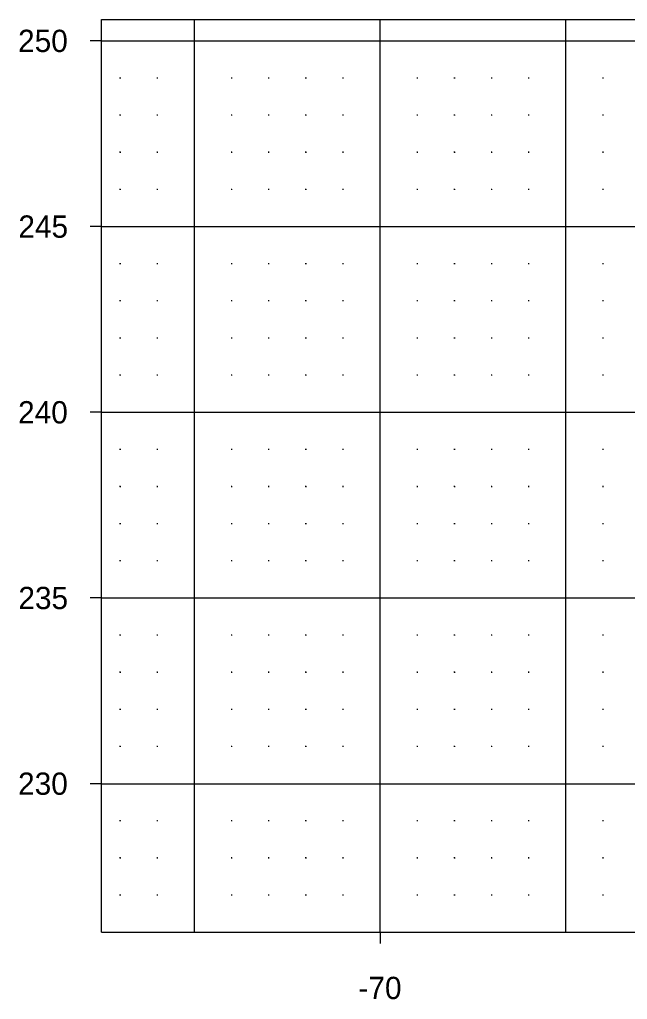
# Model space of a CAD drawing. Extents: x -80 to 80, y 222 to 253.
# Drawn here: x -79.7 to -63.34, y 224.19 to 250.57 of the extents above; entities that cross this region are included whole.
import ezdxf

# ---------------------------------------------------------------- set-up
doc = ezdxf.new("R2010")
doc.units = 0
for name, color, linetype in [('DSN_DRFT_XS Border Grid', 7, 'Continuous'), ('DSN_DRFT_XS Grid Annotations', 7, 'Continuous'), ('DSN_DRFT_XS Grid Major', 7, 'Continuous'), ('DSN_DRFT_XS Grid Minor', 7, 'Continuous')]:
    doc.layers.add(name, color=color, linetype=linetype)

msp = doc.modelspace()

# ---------------------------------------------------------------- linework, layer by layer
at = {"layer": 'DSN_DRFT_XS Border Grid'}
for p, q in [((-77.5, 250.573), (77.5, 250.573)), ((-77.5, 226), (-77.5, 250.573)), ((-77.5, 226), (77.5, 226))]:
    msp.add_line(p, q, dxfattribs=at)
at = {"layer": 'DSN_DRFT_XS Grid Major'}
for p, q in [((-75, 226), (-75, 250.573)), ((-70, 226), (-70, 250.573)), ((-65, 226), (-65, 250.573)), ((-77.5, 250), (-77.8, 250)), ((-77.5, 250), (77.5, 250)), ((-77.5, 245), (-77.8, 245)), ((-77.5, 245), (77.5, 245)), ((-77.5, 240), (-77.8, 240)), ((-77.5, 240), (77.5, 240)), ((-77.5, 235), (-77.8, 235)), ((-77.5, 235), (77.5, 235)), ((-77.5, 230), (-77.8, 230)), ((-77.5, 230), (77.5, 230)), ((-70, 226), (-70, 225.7))]:
    msp.add_line(p, q, dxfattribs=at)
at = {"layer": 'DSN_DRFT_XS Grid Minor'}
for p, q in [((-76.988, 249), (-77.012, 249)), ((-77, 249.012), (-77, 248.988)), ((-75.988, 249), (-76.012, 249)), ((-76, 249.012), (-76, 248.988)), ((-73.988, 249), (-74.012, 249)), ((-74, 249.012), (-74, 248.988)), ((-72.988, 249), (-73.012, 249)), ((-73, 249.012), (-73, 248.988)), ((-71.988, 249), (-72.012, 249)), ((-72, 249.012), (-72, 248.988)), ((-70.988, 249), (-71.012, 249)), ((-71, 249.012), (-71, 248.988)), ((-68.988, 249), (-69.012, 249)), ((-69, 249.012), (-69, 248.988)), ((-67.988, 249), (-68.012, 249)), ((-68, 249.012), (-68, 248.988)), ((-66.988, 249), (-67.012, 249)), ((-67, 249.012), (-67, 248.988)), ((-65.988, 249), (-66.012, 249)), ((-66, 249.012), (-66, 248.988)), ((-63.988, 249), (-64.012, 249)), ((-64, 249.012), (-64, 248.988)), ((-76.988, 248), (-77.012, 248)), ((-77, 248.012), (-77, 247.988)), ((-75.988, 248), (-76.012, 248)), ((-76, 248.012), (-76, 247.988)), ((-73.988, 248), (-74.012, 248)), ((-74, 248.012), (-74, 247.988)), ((-72.988, 248), (-73.012, 248)), ((-73, 248.012), (-73, 247.988)), ((-71.988, 248), (-72.012, 248)), ((-72, 248.012), (-72, 247.988)), ((-70.988, 248), (-71.012, 248)), ((-71, 248.012), (-71, 247.988)), ((-68.988, 248), (-69.012, 248)), ((-69, 248.012), (-69, 247.988)), ((-67.988, 248), (-68.012, 248)), ((-68, 248.012), (-68, 247.988)), ((-66.988, 248), (-67.012, 248)), ((-67, 248.012), (-67, 247.988)), ((-65.988, 248), (-66.012, 248)), ((-66, 248.012), (-66, 247.988)), ((-63.988, 248), (-64.012, 248)), ((-64, 248.012), (-64, 247.988)), ((-76.988, 247), (-77.012, 247)), ((-77, 247.012), (-77, 246.988)), ((-75.988, 247), (-76.012, 247)), ((-76, 247.012), (-76, 246.988)), ((-73.988, 247), (-74.012, 247)), ((-74, 247.012), (-74, 246.988)), ((-72.988, 247), (-73.012, 247)), ((-73, 247.012), (-73, 246.988)), ((-71.988, 247), (-72.012, 247)), ((-72, 247.012), (-72, 246.988)), ((-70.988, 247), (-71.012, 247)), ((-71, 247.012), (-71, 246.988)), ((-68.988, 247), (-69.012, 247)), ((-69, 247.012), (-69, 246.988)), ((-67.988, 247), (-68.012, 247)), ((-68, 247.012), (-68, 246.988)), ((-66.988, 247), (-67.012, 247)), ((-67, 247.012), (-67, 246.988)), ((-65.988, 247), (-66.012, 247)), ((-66, 247.012), (-66, 246.988)), ((-63.988, 247), (-64.012, 247)), ((-64, 247.012), (-64, 246.988)), ((-76.988, 246), (-77.012, 246)), ((-77, 246.012), (-77, 245.988)), ((-75.988, 246), (-76.012, 246)), ((-76, 246.012), (-76, 245.988)), ((-73.988, 246), (-74.012, 246)), ((-74, 246.012), (-74, 245.988)), ((-72.988, 246), (-73.012, 246)), ((-73, 246.012), (-73, 245.988)), ((-71.988, 246), (-72.012, 246)), ((-72, 246.012), (-72, 245.988)), ((-70.988, 246), (-71.012, 246)), ((-71, 246.012), (-71, 245.988)), ((-68.988, 246), (-69.012, 246)), ((-69, 246.012), (-69, 245.988)), ((-67.988, 246), (-68.012, 246)), ((-68, 246.012), (-68, 245.988)), ((-66.988, 246), (-67.012, 246)), ((-67, 246.012), (-67, 245.988)), ((-65.988, 246), (-66.012, 246)), ((-66, 246.012), (-66, 245.988)), ((-63.988, 246), (-64.012, 246)), ((-64, 246.012), (-64, 245.988)), ((-76.988, 244), (-77.012, 244)), ((-77, 244.012), (-77, 243.988)), ((-75.988, 244), (-76.012, 244)), ((-76, 244.012), (-76, 243.988)), ((-73.988, 244), (-74.012, 244)), ((-74, 244.012), (-74, 243.988)), ((-72.988, 244), (-73.012, 244)), ((-73, 244.012), (-73, 243.988)), ((-71.988, 244), (-72.012, 244)), ((-72, 244.012), (-72, 243.988)), ((-70.988, 244), (-71.012, 244)), ((-71, 244.012), (-71, 243.988)), ((-68.988, 244), (-69.012, 244)), ((-69, 244.012), (-69, 243.988)), ((-67.988, 244), (-68.012, 244)), ((-68, 244.012), (-68, 243.988)), ((-66.988, 244), (-67.012, 244)), ((-67, 244.012), (-67, 243.988)), ((-65.988, 244), (-66.012, 244)), ((-66, 244.012), (-66, 243.988)), ((-63.988, 244), (-64.012, 244)), ((-64, 244.012), (-64, 243.988)), ((-76.988, 243), (-77.012, 243)), ((-77, 243.012), (-77, 242.988)), ((-75.988, 243), (-76.012, 243)), ((-76, 243.012), (-76, 242.988)), ((-73.988, 243), (-74.012, 243)), ((-74, 243.012), (-74, 242.988)), ((-72.988, 243), (-73.012, 243)), ((-73, 243.012), (-73, 242.988)), ((-71.988, 243), (-72.012, 243)), ((-72, 243.012), (-72, 242.988)), ((-70.988, 243), (-71.012, 243)), ((-71, 243.012), (-71, 242.988)), ((-68.988, 243), (-69.012, 243)), ((-69, 243.012), (-69, 242.988)), ((-67.988, 243), (-68.012, 243)), ((-68, 243.012), (-68, 242.988)), ((-66.988, 243), (-67.012, 243)), ((-67, 243.012), (-67, 242.988)), ((-65.988, 243), (-66.012, 243)), ((-66, 243.012), (-66, 242.988)), ((-63.988, 243), (-64.012, 243)), ((-64, 243.012), (-64, 242.988)), ((-76.988, 242), (-77.012, 242)), ((-77, 242.012), (-77, 241.988)), ((-75.988, 242), (-76.012, 242)), ((-76, 242.012), (-76, 241.988)), ((-73.988, 242), (-74.012, 242)), ((-74, 242.012), (-74, 241.988)), ((-72.988, 242), (-73.012, 242)), ((-73, 242.012), (-73, 241.988)), ((-71.988, 242), (-72.012, 242)), ((-72, 242.012), (-72, 241.988)), ((-70.988, 242), (-71.012, 242)), ((-71, 242.012), (-71, 241.988)), ((-68.988, 242), (-69.012, 242)), ((-69, 242.012), (-69, 241.988)), ((-67.988, 242), (-68.012, 242)), ((-68, 242.012), (-68, 241.988)), ((-66.988, 242), (-67.012, 242)), ((-67, 242.012), (-67, 241.988)), ((-65.988, 242), (-66.012, 242)), ((-66, 242.012), (-66, 241.988)), ((-63.988, 242), (-64.012, 242)), ((-64, 242.012), (-64, 241.988)), ((-76.988, 241), (-77.012, 241)), ((-77, 241.012), (-77, 240.988)), ((-75.988, 241), (-76.012, 241)), ((-76, 241.012), (-76, 240.988)), ((-73.988, 241), (-74.012, 241)), ((-74, 241.012), (-74, 240.988)), ((-72.988, 241), (-73.012, 241)), ((-73, 241.012), (-73, 240.988)), ((-71.988, 241), (-72.012, 241)), ((-72, 241.012), (-72, 240.988)), ((-70.988, 241), (-71.012, 241)), ((-71, 241.012), (-71, 240.988)), ((-68.988, 241), (-69.012, 241)), ((-69, 241.012), (-69, 240.988)), ((-67.988, 241), (-68.012, 241)), ((-68, 241.012), (-68, 240.988)), ((-66.988, 241), (-67.012, 241)), ((-67, 241.012), (-67, 240.988)), ((-65.988, 241), (-66.012, 241)), ((-66, 241.012), (-66, 240.988)), ((-63.988, 241), (-64.012, 241)), ((-64, 241.012), (-64, 240.988)), ((-76.988, 239), (-77.012, 239)), ((-77, 239.012), (-77, 238.988)), ((-75.988, 239), (-76.012, 239)), ((-76, 239.012), (-76, 238.988)), ((-73.988, 239), (-74.012, 239)), ((-74, 239.012), (-74, 238.988)), ((-72.988, 239), (-73.012, 239)), ((-73, 239.012), (-73, 238.988)), ((-71.988, 239), (-72.012, 239)), ((-72, 239.012), (-72, 238.988)), ((-70.988, 239), (-71.012, 239)), ((-71, 239.012), (-71, 238.988)), ((-68.988, 239), (-69.012, 239)), ((-69, 239.012), (-69, 238.988)), ((-67.988, 239), (-68.012, 239)), ((-68, 239.012), (-68, 238.988)), ((-66.988, 239), (-67.012, 239)), ((-67, 239.012), (-67, 238.988)), ((-65.988, 239), (-66.012, 239)), ((-66, 239.012), (-66, 238.988)), ((-63.988, 239), (-64.012, 239)), ((-64, 239.012), (-64, 238.988)), ((-76.988, 238), (-77.012, 238)), ((-77, 238.012), (-77, 237.988)), ((-75.988, 238), (-76.012, 238)), ((-76, 238.012), (-76, 237.988)), ((-73.988, 238), (-74.012, 238)), ((-74, 238.012), (-74, 237.988)), ((-72.988, 238), (-73.012, 238)), ((-73, 238.012), (-73, 237.988)), ((-71.988, 238), (-72.012, 238)), ((-72, 238.012), (-72, 237.988)), ((-70.988, 238), (-71.012, 238)), ((-71, 238.012), (-71, 237.988)), ((-68.988, 238), (-69.012, 238)), ((-69, 238.012), (-69, 237.988)), ((-67.988, 238), (-68.012, 238)), ((-68, 238.012), (-68, 237.988)), ((-66.988, 238), (-67.012, 238)), ((-67, 238.012), (-67, 237.988)), ((-65.988, 238), (-66.012, 238)), ((-66, 238.012), (-66, 237.988)), ((-63.988, 238), (-64.012, 238)), ((-64, 238.012), (-64, 237.988)), ((-76.988, 237), (-77.012, 237)), ((-77, 237.012), (-77, 236.988)), ((-75.988, 237), (-76.012, 237)), ((-76, 237.012), (-76, 236.988)), ((-73.988, 237), (-74.012, 237)), ((-74, 237.012), (-74, 236.988)), ((-72.988, 237), (-73.012, 237)), ((-73, 237.012), (-73, 236.988)), ((-71.988, 237), (-72.012, 237)), ((-72, 237.012), (-72, 236.988)), ((-70.988, 237), (-71.012, 237)), ((-71, 237.012), (-71, 236.988)), ((-68.988, 237), (-69.012, 237)), ((-69, 237.012), (-69, 236.988)), ((-67.988, 237), (-68.012, 237)), ((-68, 237.012), (-68, 236.988)), ((-66.988, 237), (-67.012, 237)), ((-67, 237.012), (-67, 236.988)), ((-65.988, 237), (-66.012, 237)), ((-66, 237.012), (-66, 236.988)), ((-63.988, 237), (-64.012, 237)), ((-64, 237.012), (-64, 236.988)), ((-76.988, 236), (-77.012, 236)), ((-77, 236.012), (-77, 235.988)), ((-75.988, 236), (-76.012, 236)), ((-76, 236.012), (-76, 235.988)), ((-73.988, 236), (-74.012, 236)), ((-74, 236.012), (-74, 235.988)), ((-72.988, 236), (-73.012, 236)), ((-73, 236.012), (-73, 235.988)), ((-71.988, 236), (-72.012, 236)), ((-72, 236.012), (-72, 235.988)), ((-70.988, 236), (-71.012, 236)), ((-71, 236.012), (-71, 235.988)), ((-68.988, 236), (-69.012, 236)), ((-69, 236.012), (-69, 235.988)), ((-67.988, 236), (-68.012, 236)), ((-68, 236.012), (-68, 235.988)), ((-66.988, 236), (-67.012, 236)), ((-67, 236.012), (-67, 235.988)), ((-65.988, 236), (-66.012, 236)), ((-66, 236.012), (-66, 235.988)), ((-63.988, 236), (-64.012, 236)), ((-64, 236.012), (-64, 235.988)), ((-77, 234.012), (-77, 233.988)), ((-76, 234.012), (-76, 233.988)), ((-74, 234.012), (-74, 233.988)), ((-73, 234.012), (-73, 233.988)), ((-72, 234.012), (-72, 233.988)), ((-71, 234.012), (-71, 233.988)), ((-69, 234.012), (-69, 233.988)), ((-68, 234.012), (-68, 233.988)), ((-67, 234.012), (-67, 233.988)), ((-66, 234.012), (-66, 233.988)), ((-64, 234.012), (-64, 233.988)), ((-76.988, 234), (-77.012, 234)), ((-75.988, 234), (-76.012, 234)), ((-73.988, 234), (-74.012, 234)), ((-72.988, 234), (-73.012, 234)), ((-71.988, 234), (-72.012, 234)), ((-70.988, 234), (-71.012, 234)), ((-68.988, 234), (-69.012, 234)), ((-67.988, 234), (-68.012, 234)), ((-66.988, 234), (-67.012, 234)), ((-65.988, 234), (-66.012, 234)), ((-63.988, 234), (-64.012, 234)), ((-76.988, 233), (-77.012, 233)), ((-77, 233.012), (-77, 232.988)), ((-75.988, 233), (-76.012, 233)), ((-76, 233.012), (-76, 232.988)), ((-73.988, 233), (-74.012, 233)), ((-74, 233.012), (-74, 232.988)), ((-72.988, 233), (-73.012, 233)), ((-73, 233.012), (-73, 232.988)), ((-71.988, 233), (-72.012, 233)), ((-72, 233.012), (-72, 232.988)), ((-70.988, 233), (-71.012, 233)), ((-71, 233.012), (-71, 232.988)), ((-68.988, 233), (-69.012, 233)), ((-69, 233.012), (-69, 232.988)), ((-67.988, 233), (-68.012, 233)), ((-68, 233.012), (-68, 232.988)), ((-66.988, 233), (-67.012, 233)), ((-67, 233.012), (-67, 232.988)), ((-65.988, 233), (-66.012, 233)), ((-66, 233.012), (-66, 232.988)), ((-63.988, 233), (-64.012, 233)), ((-64, 233.012), (-64, 232.988)), ((-76.988, 232), (-77.012, 232)), ((-77, 232.012), (-77, 231.988)), ((-75.988, 232), (-76.012, 232)), ((-76, 232.012), (-76, 231.988)), ((-73.988, 232), (-74.012, 232)), ((-74, 232.012), (-74, 231.988)), ((-72.988, 232), (-73.012, 232)), ((-73, 232.012), (-73, 231.988)), ((-71.988, 232), (-72.012, 232)), ((-72, 232.012), (-72, 231.988)), ((-70.988, 232), (-71.012, 232)), ((-71, 232.012), (-71, 231.988)), ((-68.988, 232), (-69.012, 232)), ((-69, 232.012), (-69, 231.988)), ((-67.988, 232), (-68.012, 232)), ((-68, 232.012), (-68, 231.988)), ((-66.988, 232), (-67.012, 232)), ((-67, 232.012), (-67, 231.988)), ((-65.988, 232), (-66.012, 232)), ((-66, 232.012), (-66, 231.988)), ((-63.988, 232), (-64.012, 232)), ((-64, 232.012), (-64, 231.988)), ((-76.988, 231), (-77.012, 231)), ((-77, 231.012), (-77, 230.988)), ((-75.988, 231), (-76.012, 231)), ((-76, 231.012), (-76, 230.988)), ((-73.988, 231), (-74.012, 231)), ((-74, 231.012), (-74, 230.988)), ((-72.988, 231), (-73.012, 231)), ((-73, 231.012), (-73, 230.988)), ((-71.988, 231), (-72.012, 231)), ((-72, 231.012), (-72, 230.988)), ((-70.988, 231), (-71.012, 231)), ((-71, 231.012), (-71, 230.988)), ((-68.988, 231), (-69.012, 231)), ((-69, 231.012), (-69, 230.988)), ((-67.988, 231), (-68.012, 231)), ((-68, 231.012), (-68, 230.988)), ((-66.988, 231), (-67.012, 231)), ((-67, 231.012), (-67, 230.988)), ((-65.988, 231), (-66.012, 231)), ((-66, 231.012), (-66, 230.988)), ((-63.988, 231), (-64.012, 231)), ((-64, 231.012), (-64, 230.988)), ((-76.988, 229), (-77.012, 229)), ((-77, 229.012), (-77, 228.988)), ((-75.988, 229), (-76.012, 229)), ((-76, 229.012), (-76, 228.988)), ((-73.988, 229), (-74.012, 229)), ((-74, 229.012), (-74, 228.988)), ((-72.988, 229), (-73.012, 229)), ((-73, 229.012), (-73, 228.988)), ((-71.988, 229), (-72.012, 229)), ((-72, 229.012), (-72, 228.988)), ((-70.988, 229), (-71.012, 229)), ((-71, 229.012), (-71, 228.988)), ((-68.988, 229), (-69.012, 229)), ((-69, 229.012), (-69, 228.988)), ((-67.988, 229), (-68.012, 229)), ((-68, 229.012), (-68, 228.988)), ((-66.988, 229), (-67.012, 229)), ((-67, 229.012), (-67, 228.988)), ((-65.988, 229), (-66.012, 229)), ((-66, 229.012), (-66, 228.988)), ((-63.988, 229), (-64.012, 229)), ((-64, 229.012), (-64, 228.988)), ((-76.988, 228), (-77.012, 228)), ((-77, 228.012), (-77, 227.988)), ((-75.988, 228), (-76.012, 228)), ((-76, 228.012), (-76, 227.988)), ((-73.988, 228), (-74.012, 228)), ((-74, 228.012), (-74, 227.988)), ((-72.988, 228), (-73.012, 228)), ((-73, 228.012), (-73, 227.988)), ((-71.988, 228), (-72.012, 228)), ((-72, 228.012), (-72, 227.988)), ((-70.988, 228), (-71.012, 228)), ((-71, 228.012), (-71, 227.988)), ((-68.988, 228), (-69.012, 228)), ((-69, 228.012), (-69, 227.988)), ((-67.988, 228), (-68.012, 228)), ((-68, 228.012), (-68, 227.988)), ((-66.988, 228), (-67.012, 228)), ((-67, 228.012), (-67, 227.988)), ((-65.988, 228), (-66.012, 228)), ((-66, 228.012), (-66, 227.988)), ((-63.988, 228), (-64.012, 228)), ((-64, 228.012), (-64, 227.988)), ((-76.988, 227), (-77.012, 227)), ((-77, 227.012), (-77, 226.988)), ((-75.988, 227), (-76.012, 227)), ((-76, 227.012), (-76, 226.988)), ((-73.988, 227), (-74.012, 227)), ((-74, 227.012), (-74, 226.988)), ((-72.988, 227), (-73.012, 227)), ((-73, 227.012), (-73, 226.988)), ((-71.988, 227), (-72.012, 227)), ((-72, 227.012), (-72, 226.988)), ((-70.988, 227), (-71.012, 227)), ((-71, 227.012), (-71, 226.988)), ((-68.988, 227), (-69.012, 227)), ((-69, 227.012), (-69, 226.988)), ((-67.988, 227), (-68.012, 227)), ((-68, 227.012), (-68, 226.988)), ((-66.988, 227), (-67.012, 227)), ((-67, 227.012), (-67, 226.988)), ((-65.988, 227), (-66.012, 227)), ((-66, 227.012), (-66, 226.988)), ((-63.988, 227), (-64.012, 227)), ((-64, 227.012), (-64, 226.988))]:
    msp.add_line(p, q, dxfattribs=at)

# ---------------------------------------------------------------- texts
at = {"layer": 'DSN_DRFT_XS Grid Annotations'}
for s, p in [('250', (-79.745, 249.7)), ('245', (-79.737, 244.7)), ('240', (-79.745, 239.7)), ('235', (-79.737, 234.7)), ('230', (-79.745, 229.7)), ('-70', (-70.581, 224.2))]:
    msp.add_text(s, height=0.6, dxfattribs=at).set_placement(p)

doc.saveas('drawing.dxf')
